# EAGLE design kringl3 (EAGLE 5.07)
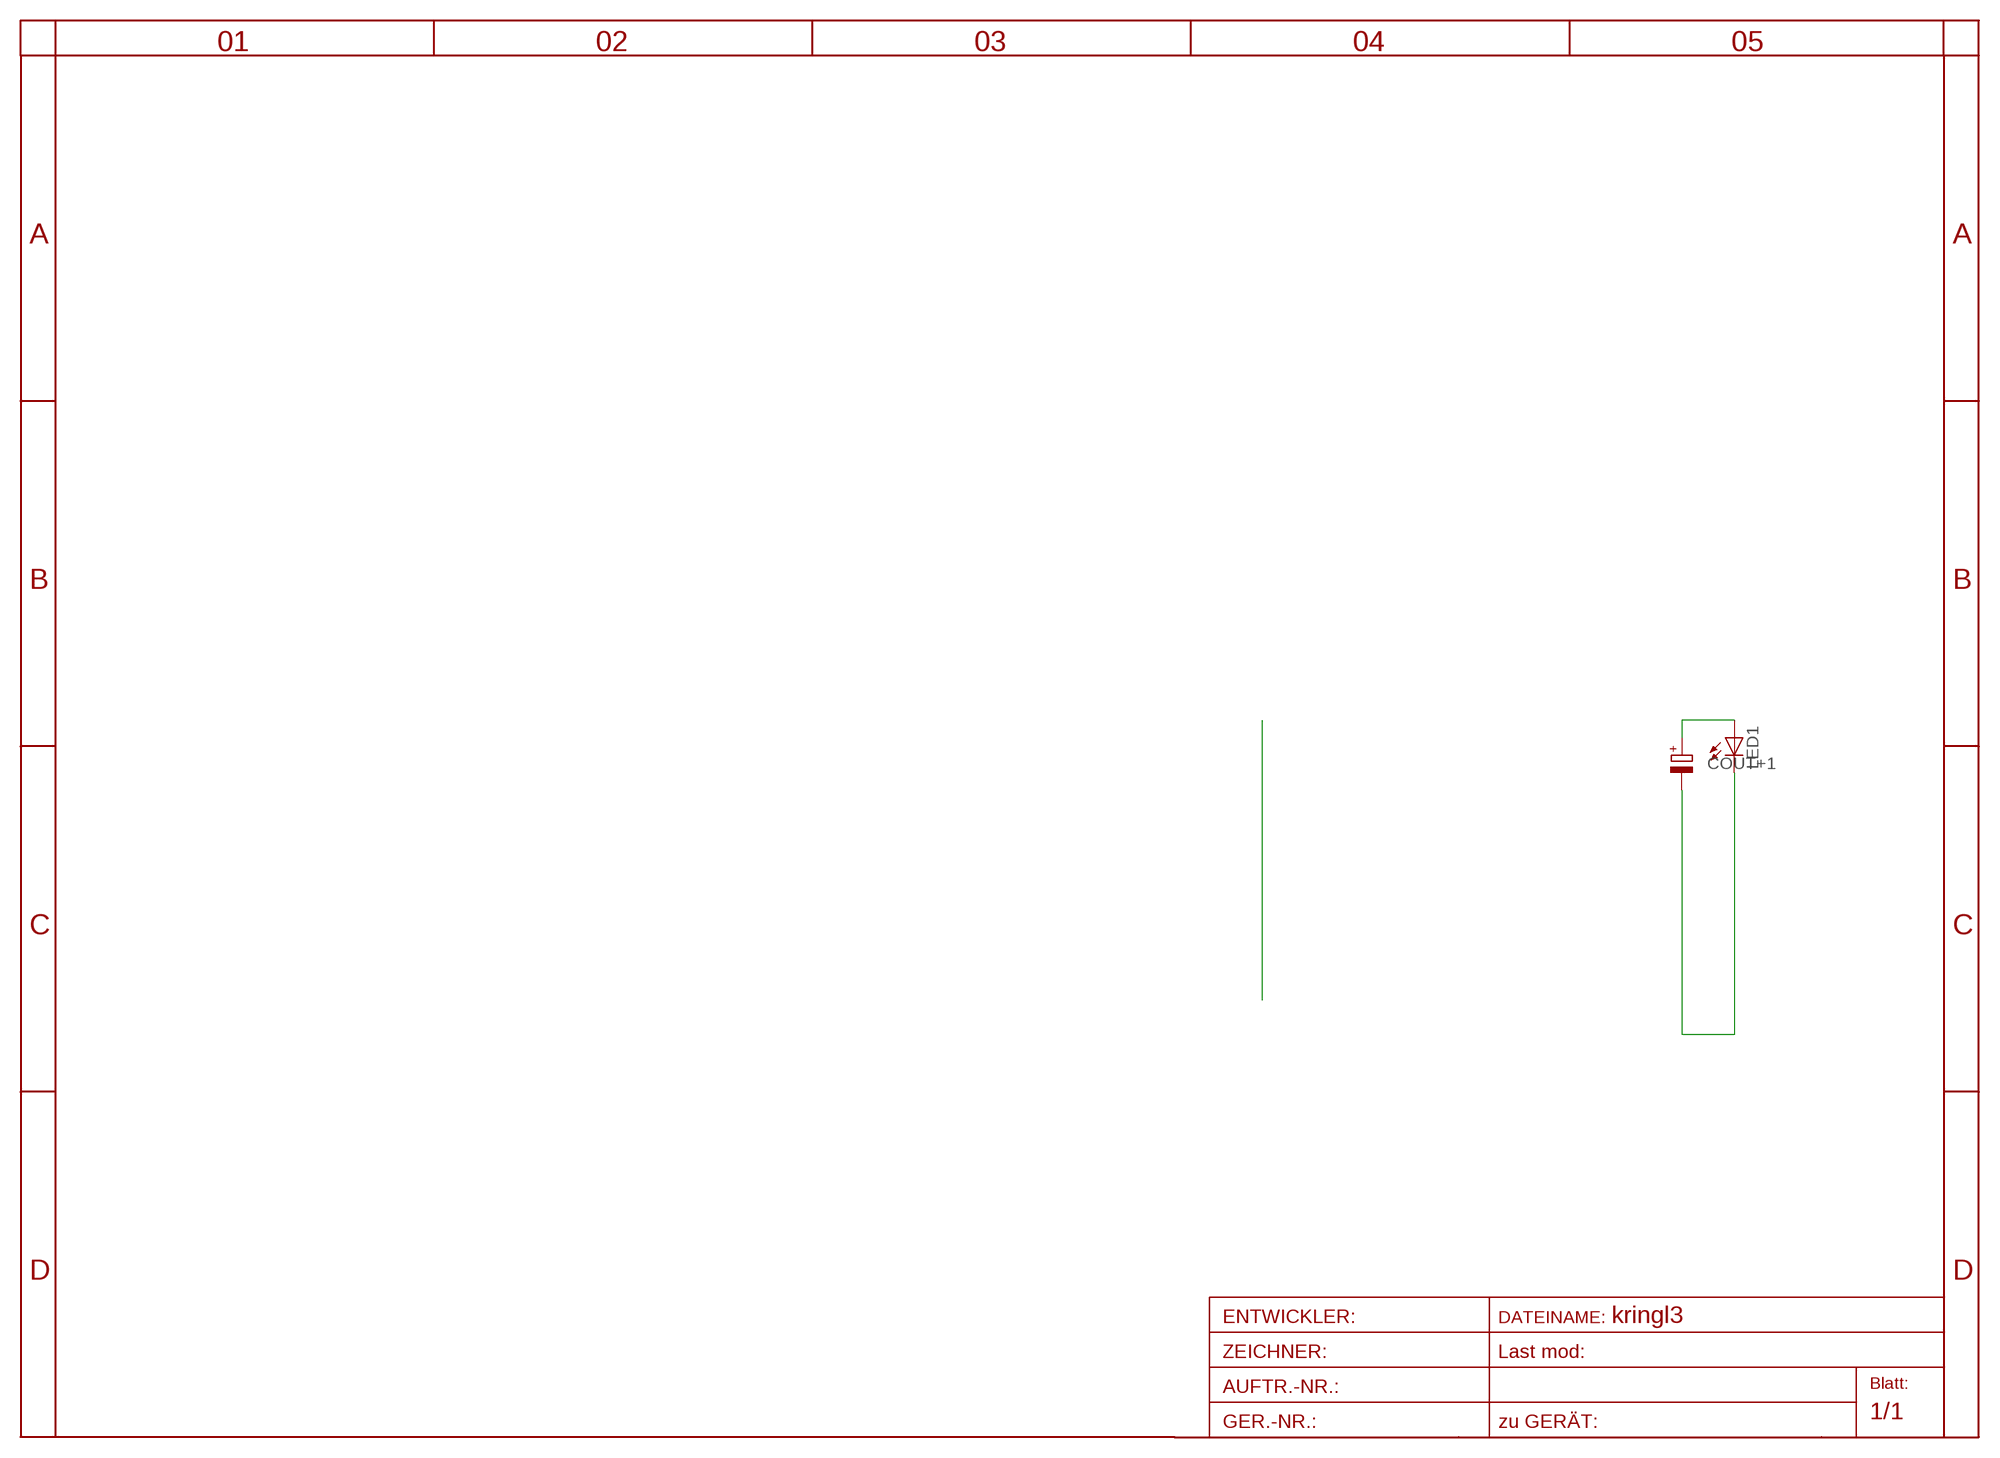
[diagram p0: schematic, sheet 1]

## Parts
COUT+1  CPOL-EUE7.5-16  [E7,5-16]
LED1  LED1W1MM6  [1W1MM6]

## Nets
A: COUT+1.+ LED1.A
C: COUT+1.- LED1.C

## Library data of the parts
COUT+1 = rcl:CPOL-EU: POLARIZED CAPACITOR, European symbol
LED1 = led:LED: LED

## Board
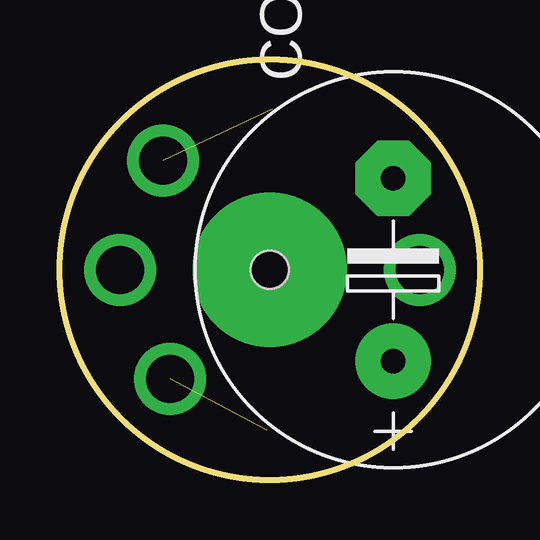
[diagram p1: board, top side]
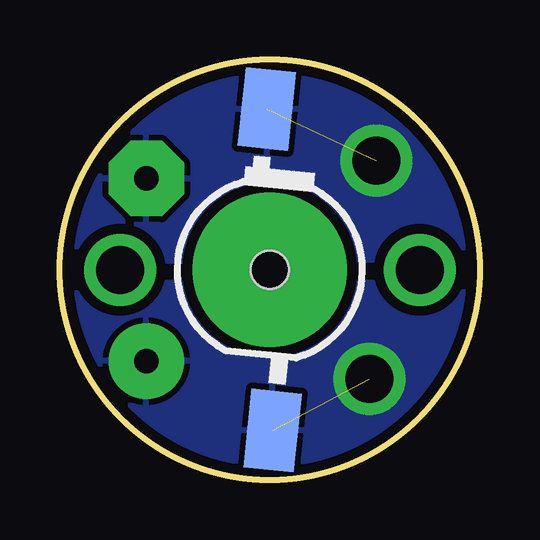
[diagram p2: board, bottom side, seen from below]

Size 17.5 x 17.5 mm. Coordinates in mm from the lower left corner, seen from the top.
Outline: circle at 8.75,8.75 radius 8.75
Copper layers (1*16): Top 0.035mm / dielectric 1.5mm / Bottom 0.035mm
Design rules "default *": minimum track width 10mil, minimum drill 20mil, track to track 8mil, track to pad 8mil, pad to pad 8mil, via to via 8mil, smd to smd 8mil, copper to edge 8mil, drill to drill 8mil, minimum pad ring 8mil, minimum via ring 8mil, stop-mask expansion 8mil, vias tented up to drill 0mil, thermal gap 10mil

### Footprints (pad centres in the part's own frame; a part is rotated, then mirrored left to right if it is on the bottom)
E7,5-16 = drill 1.016 pad 3.15 round: + -3.81,0 | drill 1.016 pad 3.15 octagon: - 3.81,0
1W1MM6 = smd 3.3 x 2.1: A -6.65,-0.82; C 6.65,0.82 | drill 1.6 pad 6.452 round: P$1 0,0 | hole 1.6: 0,0

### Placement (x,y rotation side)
COUT+1  13.9,8.75 90 top
LED1  8.75,8.75 84 bottom

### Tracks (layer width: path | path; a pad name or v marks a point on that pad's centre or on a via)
A  (via drill 2)  (1 unrouted)
  other vias: 4.6,4.2
  pour Bottom (isolate 0.406): 0.3,8.2 17.2,8.2 16.5,6.1 arc-161
C  (via drill 2)  (1 unrouted)
  other vias: 4.3,13.3
  pour Bottom (isolate 0.406): 0.2,9.2 arc-158 16.1,12.2 17.3,9.1
N$2  (via drill 2)
  other vias: 2.5,8.75
N$4  (via drill 2)
  other vias: 15,8.75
